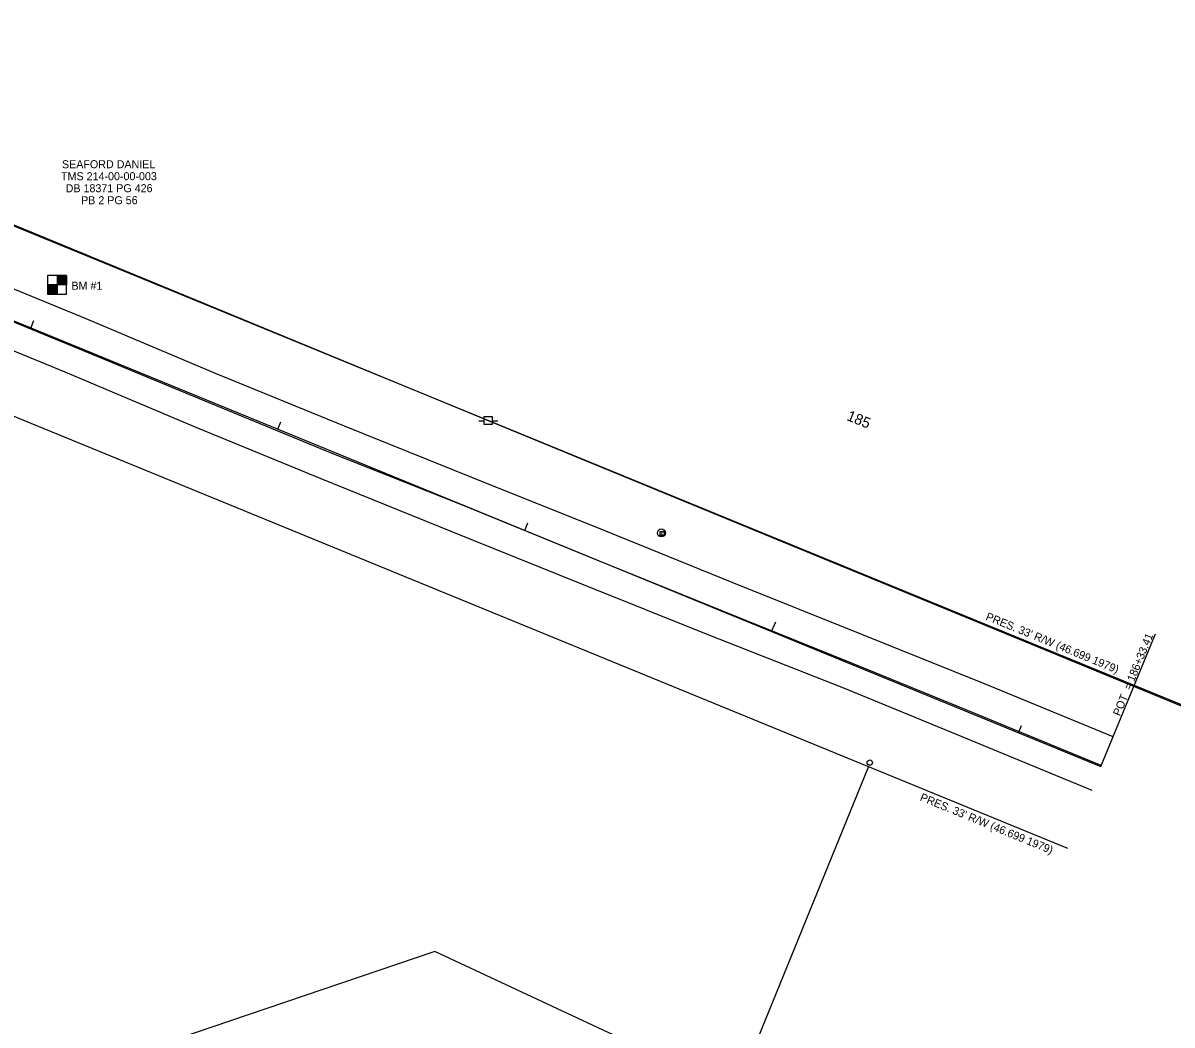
# Model space of a CAD drawing. Extents: x 1903662 to 1907233, y 1108998 to 1112872.
# Drawn here: x 1905817.9 to 1906248.5, y 1109706.1 to 1110081.7 of the extents above; entities that cross this region are included whole.
import ezdxf

# ---------------------------------------------------------------- set-up
doc = ezdxf.new("R2010")
doc.units = 0
for name, color, linetype in [('RD_DTM_BkLn1', 7, 'Continuous'), ('RD_EX_DV_Prop', 7, 'Continuous'), ('RD_EX_DV_PropPin', 7, 'Continuous'), ('RD_EX_DV_TX_Prop', 7, 'Continuous'), ('RD_EX_Road', 7, 'Continuous'), ('RD_EX_RW', 7, 'Continuous'), ('RD_EX_RW_TX', 7, 'Continuous'), ('RD_EX_UT', 7, 'Continuous'), ('RD_HC_Cl', 7, 'Continuous'), ('RD_HC_Data', 7, 'Continuous'), ('RD_HC_Data_Tic', 7, 'Continuous'), ('RD_HC_Survey', 7, 'Continuous'), ('RD_HC_Survey_txCode', 7, 'Continuous'), ('RD_HC_TX_Sta20', 7, 'Continuous'), ('SV_UT_Electric_Appurt', 7, 'Continuous'), ('SV_UT_Electric_Lines', 7, 'Continuous'), ('SV_UT_Tele_Appurt', 7, 'Continuous')]:
    doc.layers.add(name, color=color, linetype=linetype)

msp = doc.modelspace()

# ---------------------------------------------------------------- linework, layer by layer
at = {"layer": 'RD_DTM_BkLn1'}
msp.add_lwpolyline([(1905686.48, 1110022.61), (1905738.58, 1110001.31), (1905787.5, 1109980.72), (1905836.79, 1109960.49), (1905886.09, 1109940.06), (1905933.61, 1109920.5), (1905982.43, 1109901.08), (1906031.95, 1109880.93), (1906079.41, 1109861.63), (1906128.68, 1109841.73), (1906173.54, 1109823.42), (1906221.88, 1109803.54)], dxfattribs=at)
at = {"layer": 'RD_EX_DV_Prop'}
msp.add_lwpolyline([(1906134.79, 1109803.04), (1906085.04, 1109681.02), (1905972.27, 1109733.72), (1905818.66, 1109681.58), (1905711.89, 1109606.46), (1905677.41, 1109545.61), (1905342.86, 1109682.01), (1905463.07, 1109889.61), (1905568.32, 1110035.23)], dxfattribs=at)
at = {"layer": 'RD_EX_DV_PropPin'}
msp.add_circle((1906135.21, 1109804.51), 1, dxfattribs=at)
at = {"layer": 'RD_EX_Road'}
for points in [[(1905690.58, 1110032.38), (1905740.94, 1110012.84), (1905792.12, 1109991.14), (1905841.47, 1109970.96), (1905889.9, 1109950.42), (1905938.3, 1109930.68), (1905985.99, 1109911.49), (1906036.2, 1109891.33), (1906083.57, 1109872.1), (1906132.15, 1109852.67), (1906178.06, 1109834.09), (1906226.28, 1109814.29)], [(1905682.83, 1110013.58), (1905734.66, 1109991.82), (1905783.64, 1109971.5), (1905833.5, 1109950.95), (1905881.99, 1109930.52), (1905929.54, 1109910.92), (1905978.23, 1109891.27), (1906027.19, 1109871.52), (1906075.16, 1109852.25), (1906125.33, 1109832.56), (1906169.72, 1109814.29), (1906218.45, 1109794.17)]]:
    msp.add_lwpolyline(points, dxfattribs=at)
at = {"layer": 'RD_EX_RW'}
for p, q in [((1904864.32, 1110395.12), (1906497.97, 1109725.51)), ((1904839.26, 1110334.07), (1906209.37, 1109772.47))]:
    msp.add_line(p, q, dxfattribs=at)
at = {"layer": 'RD_EX_UT'}
for p, q in [((1905988.68, 1109932.63), (1905990.74, 1109932.63)), ((1905992.24, 1109932.67), (1905992.24, 1109932.67)), ((1905993.74, 1109932.63), (1905995.88, 1109932.63))]:
    msp.add_line(p, q, dxfattribs=at)
msp.add_lwpolyline([(1904589.73, 1110482.88), (1904891.43, 1110385.65), (1905171.11, 1110270.76), (1905436.6, 1110161.49), (1905735.85, 1110038.44), (1905992.24, 1109932.67), (1906258.29, 1109823.17), (1906443.47, 1109747.31)], dxfattribs=at)
for points in [[(1905990.74, 1109931.17), (1905990.74, 1109934.17), (1905993.74, 1109934.17), (1905993.74, 1109931.17)], [(1906058.19, 1109889.64), (1906056.69, 1109889.64), (1906056.69, 1109891.14), (1906058.19, 1109891.14)]]:
    msp.add_lwpolyline(points, close=True, dxfattribs=at)
msp.add_circle((1906057.12, 1109890.58), 1.5, dxfattribs=at)
at = {"layer": 'RD_HC_Cl'}
msp.add_line((1904865.19, 1110359.1), (1906221.88, 1109803.01), dxfattribs=at)
at = {"layer": 'RD_HC_Data'}
msp.add_line((1906221.88, 1109803.01), (1906242.26, 1109852.73), dxfattribs=at)
at = {"layer": 'RD_HC_Data_Tic'}
for p, q in [((1905820.85, 1109967.39), (1905821.99, 1109970.16)), ((1905913.38, 1109929.46), (1905914.52, 1109932.23)), ((1906005.91, 1109891.53), (1906007.05, 1109894.31)), ((1906098.44, 1109853.61), (1906099.96, 1109857.31)), ((1906190.97, 1109815.68), (1906192.11, 1109818.46))]:
    msp.add_line(p, q, dxfattribs=at)
at = {"layer": 'RD_HC_Survey'}
for p, q in [((1905830.66, 1109987.13), (1905830.66, 1109980.06)), ((1905830.69, 1109987.13), (1905830.69, 1109983.6)), ((1905830.74, 1109987.13), (1905830.74, 1109983.6)), ((1905830.79, 1109987.13), (1905830.79, 1109983.6)), ((1905830.84, 1109987.13), (1905830.84, 1109983.6)), ((1905830.89, 1109987.13), (1905830.89, 1109983.6)), ((1905830.94, 1109987.13), (1905830.94, 1109983.6)), ((1905830.99, 1109987.13), (1905830.99, 1109983.6)), ((1905831.04, 1109987.13), (1905831.04, 1109983.6)), ((1905831.09, 1109987.13), (1905831.09, 1109983.6)), ((1905831.14, 1109987.13), (1905831.14, 1109983.6)), ((1905831.19, 1109987.13), (1905831.19, 1109983.6)), ((1905831.24, 1109987.13), (1905831.24, 1109983.6)), ((1905831.29, 1109987.13), (1905831.29, 1109983.6)), ((1905831.34, 1109987.13), (1905831.34, 1109983.6)), ((1905831.39, 1109987.13), (1905831.39, 1109983.6)), ((1905831.44, 1109987.13), (1905831.44, 1109983.6)), ((1905831.49, 1109987.13), (1905831.49, 1109983.6)), ((1905831.54, 1109987.13), (1905831.54, 1109983.6)), ((1905831.59, 1109987.13), (1905831.59, 1109983.6)), ((1905831.64, 1109987.13), (1905831.64, 1109983.6)), ((1905831.69, 1109987.13), (1905831.69, 1109983.6)), ((1905831.74, 1109987.13), (1905831.74, 1109983.6)), ((1905831.79, 1109987.13), (1905831.79, 1109983.6)), ((1905831.84, 1109987.13), (1905831.84, 1109983.6)), ((1905831.89, 1109987.13), (1905831.89, 1109983.6)), ((1905831.94, 1109987.13), (1905831.94, 1109983.6)), ((1905831.99, 1109987.13), (1905831.99, 1109983.6)), ((1905832.04, 1109987.13), (1905832.04, 1109983.6)), ((1905832.09, 1109987.13), (1905832.09, 1109983.6)), ((1905832.14, 1109987.13), (1905832.14, 1109983.6)), ((1905832.19, 1109987.13), (1905832.19, 1109983.6)), ((1905832.24, 1109987.13), (1905832.24, 1109983.6)), ((1905832.29, 1109987.13), (1905832.29, 1109983.6)), ((1905832.34, 1109987.13), (1905832.34, 1109983.6)), ((1905832.39, 1109987.13), (1905832.39, 1109983.6)), ((1905832.44, 1109987.13), (1905832.44, 1109983.6)), ((1905832.49, 1109987.13), (1905832.49, 1109983.6)), ((1905832.54, 1109987.13), (1905832.54, 1109983.6)), ((1905832.59, 1109987.13), (1905832.59, 1109983.6)), ((1905832.64, 1109987.13), (1905832.64, 1109983.6)), ((1905832.69, 1109987.13), (1905832.69, 1109983.6)), ((1905832.74, 1109987.13), (1905832.74, 1109983.6)), ((1905832.79, 1109987.13), (1905832.79, 1109983.6)), ((1905832.84, 1109987.13), (1905832.84, 1109983.6)), ((1905832.89, 1109987.13), (1905832.89, 1109983.6)), ((1905832.94, 1109987.13), (1905832.94, 1109983.6)), ((1905832.99, 1109987.13), (1905832.99, 1109983.6)), ((1905833.04, 1109987.13), (1905833.04, 1109983.6)), ((1905833.09, 1109987.13), (1905833.09, 1109983.6)), ((1905833.14, 1109987.13), (1905833.14, 1109983.6)), ((1905833.19, 1109987.13), (1905833.19, 1109983.6)), ((1905833.24, 1109987.13), (1905833.24, 1109983.6)), ((1905833.29, 1109987.13), (1905833.29, 1109983.6)), ((1905833.34, 1109987.13), (1905833.34, 1109983.6)), ((1905833.39, 1109987.13), (1905833.39, 1109983.6)), ((1905833.44, 1109987.13), (1905833.44, 1109983.6)), ((1905833.49, 1109987.13), (1905833.49, 1109983.6)), ((1905833.54, 1109987.13), (1905833.54, 1109983.6)), ((1905833.59, 1109987.13), (1905833.59, 1109983.6)), ((1905833.64, 1109987.13), (1905833.64, 1109983.6)), ((1905833.69, 1109987.13), (1905833.69, 1109983.6)), ((1905833.74, 1109987.13), (1905833.74, 1109983.6)), ((1905833.79, 1109987.13), (1905833.79, 1109983.6)), ((1905833.84, 1109987.13), (1905833.84, 1109983.6)), ((1905833.89, 1109987.13), (1905833.89, 1109983.6)), ((1905833.94, 1109987.13), (1905833.94, 1109983.6)), ((1905833.99, 1109987.13), (1905833.99, 1109983.6)), ((1905834.04, 1109987.13), (1905834.04, 1109983.6)), ((1905834.09, 1109987.13), (1905834.09, 1109983.6)), ((1905834.14, 1109987.13), (1905834.14, 1109983.6)), ((1905834.19, 1109983.6), (1905827.12, 1109983.6)), ((1905827.12, 1109983.6), (1905827.12, 1109980.06)), ((1905827.17, 1109983.6), (1905827.17, 1109980.06)), ((1905827.22, 1109983.6), (1905827.22, 1109980.06)), ((1905827.27, 1109983.6), (1905827.27, 1109980.06)), ((1905827.32, 1109983.6), (1905827.32, 1109980.06)), ((1905827.37, 1109983.6), (1905827.37, 1109980.06)), ((1905827.42, 1109983.6), (1905827.42, 1109980.06)), ((1905827.47, 1109983.6), (1905827.47, 1109980.06)), ((1905827.52, 1109983.6), (1905827.52, 1109980.06)), ((1905827.57, 1109983.6), (1905827.57, 1109980.06)), ((1905827.62, 1109983.6), (1905827.62, 1109980.06)), ((1905827.67, 1109983.6), (1905827.67, 1109980.06)), ((1905827.72, 1109983.6), (1905827.72, 1109980.06)), ((1905827.77, 1109983.6), (1905827.77, 1109980.06)), ((1905827.82, 1109983.6), (1905827.82, 1109980.06)), ((1905827.87, 1109983.6), (1905827.87, 1109980.06)), ((1905827.92, 1109983.6), (1905827.92, 1109980.06)), ((1905827.97, 1109983.6), (1905827.97, 1109980.06)), ((1905828.02, 1109983.6), (1905828.02, 1109980.06)), ((1905828.07, 1109983.6), (1905828.07, 1109980.06)), ((1905828.12, 1109983.6), (1905828.12, 1109980.06)), ((1905828.17, 1109983.6), (1905828.17, 1109980.06)), ((1905828.22, 1109983.6), (1905828.22, 1109980.06)), ((1905828.27, 1109983.6), (1905828.27, 1109980.06)), ((1905828.32, 1109983.6), (1905828.32, 1109980.06)), ((1905828.37, 1109983.6), (1905828.37, 1109980.06)), ((1905828.42, 1109983.6), (1905828.42, 1109980.06)), ((1905828.47, 1109983.6), (1905828.47, 1109980.06)), ((1905828.52, 1109983.6), (1905828.52, 1109980.06)), ((1905828.57, 1109983.6), (1905828.57, 1109980.06)), ((1905828.62, 1109983.6), (1905828.62, 1109980.06)), ((1905828.67, 1109983.6), (1905828.67, 1109980.06)), ((1905828.72, 1109983.6), (1905828.72, 1109980.06)), ((1905828.77, 1109983.6), (1905828.77, 1109980.06)), ((1905828.82, 1109983.6), (1905828.82, 1109980.06)), ((1905828.87, 1109983.6), (1905828.87, 1109980.06)), ((1905828.92, 1109983.6), (1905828.92, 1109980.06)), ((1905828.97, 1109983.6), (1905828.97, 1109980.06)), ((1905829.02, 1109983.6), (1905829.02, 1109980.06)), ((1905829.07, 1109983.6), (1905829.07, 1109980.06)), ((1905829.12, 1109983.6), (1905829.12, 1109980.06)), ((1905829.17, 1109983.6), (1905829.17, 1109980.06)), ((1905829.22, 1109983.6), (1905829.22, 1109980.06)), ((1905829.27, 1109983.6), (1905829.27, 1109980.06)), ((1905829.32, 1109983.6), (1905829.32, 1109980.06)), ((1905829.37, 1109983.6), (1905829.37, 1109980.06)), ((1905829.42, 1109983.6), (1905829.42, 1109980.06)), ((1905829.47, 1109983.6), (1905829.47, 1109980.06)), ((1905829.52, 1109983.6), (1905829.52, 1109980.06)), ((1905829.57, 1109983.6), (1905829.57, 1109980.06)), ((1905829.62, 1109983.6), (1905829.62, 1109980.06)), ((1905829.67, 1109983.6), (1905829.67, 1109980.06)), ((1905829.72, 1109983.6), (1905829.72, 1109980.06)), ((1905829.77, 1109983.6), (1905829.77, 1109980.06)), ((1905829.82, 1109983.6), (1905829.82, 1109980.06)), ((1905829.87, 1109983.6), (1905829.87, 1109980.06)), ((1905829.92, 1109983.6), (1905829.92, 1109980.06)), ((1905829.97, 1109983.6), (1905829.97, 1109980.06)), ((1905830.02, 1109983.6), (1905830.02, 1109980.06)), ((1905830.07, 1109983.6), (1905830.07, 1109980.06)), ((1905830.12, 1109983.6), (1905830.12, 1109980.06)), ((1905830.17, 1109983.6), (1905830.17, 1109980.06)), ((1905830.22, 1109983.6), (1905830.22, 1109980.06)), ((1905830.27, 1109983.6), (1905830.27, 1109980.06)), ((1905830.32, 1109983.6), (1905830.32, 1109980.06)), ((1905830.37, 1109983.6), (1905830.37, 1109980.06)), ((1905830.42, 1109983.6), (1905830.42, 1109980.06)), ((1905830.47, 1109983.6), (1905830.47, 1109980.06)), ((1905830.52, 1109983.6), (1905830.52, 1109980.06)), ((1905830.57, 1109983.6), (1905830.57, 1109980.06)), ((1905830.62, 1109983.6), (1905830.62, 1109980.06))]:
    msp.add_line(p, q, dxfattribs=at)
msp.add_lwpolyline([(1905834.19, 1109987.13), (1905827.12, 1109987.13), (1905827.12, 1109980.06), (1905834.19, 1109980.06)], close=True, dxfattribs=at)
at = {"layer": 'SV_UT_Electric_Appurt'}
msp.add_lwpolyline([(1906058.19, 1109889.64), (1906056.69, 1109889.64), (1906056.69, 1109891.14), (1906058.19, 1109891.14)], close=True, dxfattribs=at)
at = {"layer": 'SV_UT_Electric_Lines'}
msp.add_lwpolyline([(1904589.73, 1110482.88), (1904891.43, 1110385.65), (1905171.11, 1110270.76), (1905436.6, 1110161.49), (1905735.85, 1110038.44), (1905992.24, 1109932.67), (1906258.29, 1109823.17), (1906443.47, 1109747.31)], dxfattribs=at)
at = {"layer": 'SV_UT_Tele_Appurt'}
msp.add_circle((1906057.12, 1109890.58), 1.5, dxfattribs=at)

# ---------------------------------------------------------------- texts
at = {"layer": 'RD_EX_DV_TX_Prop'}
for s, p in [('SEAFORD DANIEL', (1905832.49, 1110027.26)), ('TMS 214-00-00-003', (1905832.14, 1110022.76)), ('DB 18371 PG 426', (1905833.87, 1110018.26)), ('PB 2 PG 56', (1905839.66, 1110013.77))]:
    msp.add_text(s, height=3, rotation=0.0605, dxfattribs=at).set_placement(p)
at = {"layer": 'RD_EX_RW_TX'}
for p in [(1906178.43, 1109858.11), (1906153.78, 1109790.39)]:
    msp.add_text("PRES. 33' R/W (46.699 1979)", height=3, rotation=337.7118, dxfattribs=at).set_placement(p)
at = {"layer": 'RD_EX_UT'}
for s, height, p in [('T', 1.5, (1906056.76, 1109889.76)), ('E', 1, (1906056.97, 1109889.92))]:
    msp.add_text(s, height=height, rotation=360, dxfattribs=at).set_placement(p)
at = {"layer": 'RD_HC_Data'}
msp.add_text('POT  = 186+33.41', height=3, rotation=67.7118, dxfattribs=at).set_placement((1906229, 1109821.7))
at = {"layer": 'RD_HC_Survey_txCode'}
msp.add_text('BM #1', height=3, dxfattribs=at).set_placement((1905836.03, 1109981.73))
at = {"layer": 'RD_HC_TX_Sta20'}
msp.add_text('185', height=4, rotation=337.7118, dxfattribs=at).set_placement((1906126.27, 1109932.98))
at = {"layer": 'SV_UT_Electric_Appurt'}
msp.add_text('E', height=1, rotation=360, dxfattribs=at).set_placement((1906056.97, 1109889.92))
at = {"layer": 'SV_UT_Tele_Appurt'}
msp.add_text('T', height=1.5, rotation=360, dxfattribs=at).set_placement((1906056.76, 1109889.76))

doc.saveas('drawing.dxf')
